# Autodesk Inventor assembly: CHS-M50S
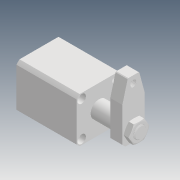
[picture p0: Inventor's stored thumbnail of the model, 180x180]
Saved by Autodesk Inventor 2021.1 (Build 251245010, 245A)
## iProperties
Created: 2019-04
Part Number: CHS-M50S
Description: STEP AP203
Document SubType Name: Assembly
Designer: user
Title: chs-m50s_asm.STEP
Revision Number: ÈÎºÎ
Sending System: SolidWorks 2017
Preprocessor: SwSTEP 2.0
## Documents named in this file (6)
- D:\Vault_2016\Projekty\Clamptek\Hydraulic\CHS\CHS-50\Inventor\CHS-M50S\CHS-M50S.iam
- D:\Vault_2016\Projekty\Clamptek\Hydraulic\CHS\CHS-50\Inventor\CHS-M50S\CHS-M50BT_1.ipt
- D:\Vault_2016\Projekty\Clamptek\Hydraulic\CHS\CHS-50\Inventor\CHS-M50S\CHS-50SHSG_5.ipt
- D:\Vault_2016\Projekty\Clamptek\Hydraulic\CHS\CHS-50\Inventor\CHS-M50S\M6_5.ipt
- D:\Vault_2016\Projekty\Clamptek\Hydraulic\CHS\CHS-50\Inventor\CHS-M50S\CHS-50SYB_6.ipt
- D:\Vault_2016\Projekty\Clamptek\Hydraulic\CHS\CHS-50\Inventor\CHS-M50S\M20LM_6.ipt
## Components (6 placed, 6 different names)
1. CHS-M50BT_1_1
2. CHS-50SHSG_5_2
3. M6_5_3
4. M6_5_4
5. CHS-50SYB_6_5
6. M20LM_6_6
